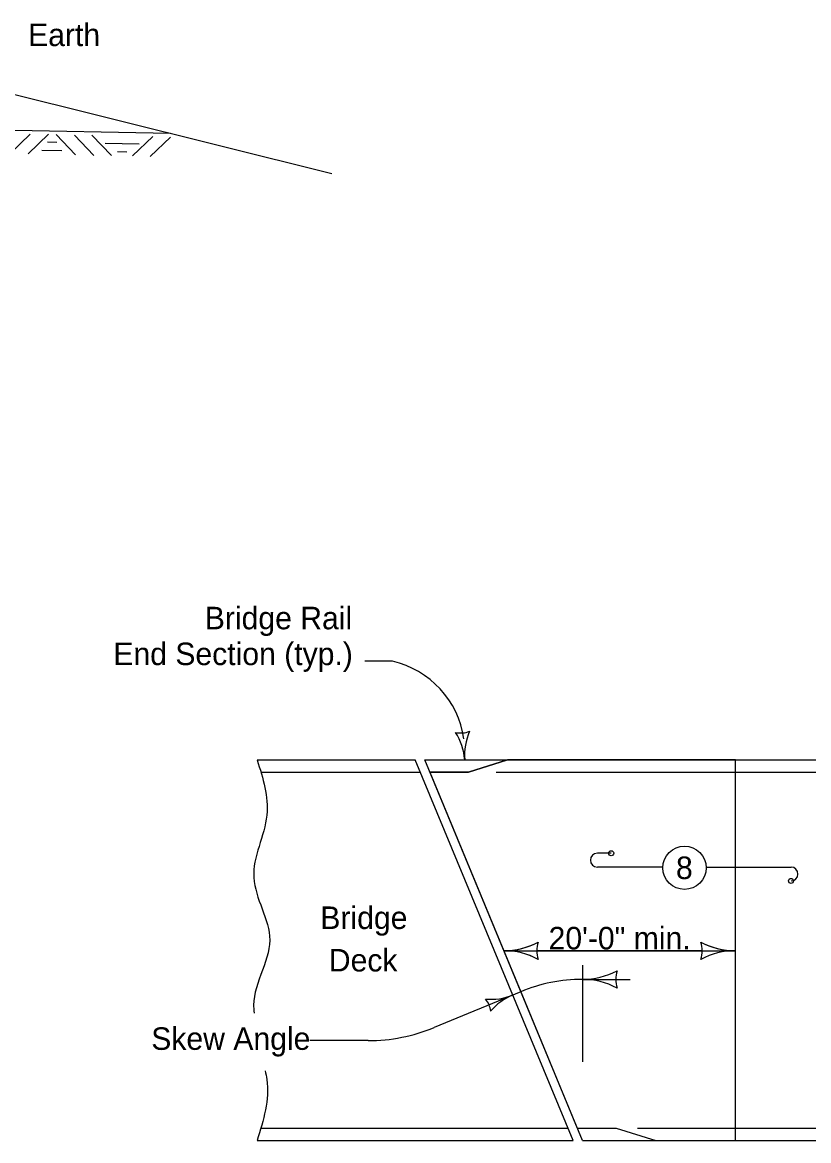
# Model space of a CAD drawing. Extents: x -2135039 to -2124495, y -2139046 to -2132546.
# Drawn here: x -2126600 to -2126042, y -2138086 to -2137292 of the extents above; entities that cross this region are included whole.
import ezdxf

# ---------------------------------------------------------------- set-up
doc = ezdxf.new("R2010")
doc.units = 0
for name, color, linetype in [('BridgeSuperStructureExisting', 7, 'Continuous'), ('dsnCellElements', 7, 'Continuous'), ('dsnStdLabel', 7, 'Continuous')]:
    doc.layers.add(name, color=color, linetype=linetype)

msp = doc.modelspace()

# ---------------------------------------------------------------- linework, layer by layer
at = {"layer": 'BridgeSuperStructureExisting'}
for p, q in [((-2126628.92, -2137337.22), (-2126380.66, -2137399.31)), ((-2126673.14, -2137367.07), (-2126495.29, -2137370.64)), ((-2126594.91, -2137371.29), (-2126609.33, -2137385.15)), ((-2126581.9, -2137371.33), (-2126596.32, -2137385.18)), ((-2126576.49, -2137371.44), (-2126562.63, -2137385.86)), ((-2126563.49, -2137371.92), (-2126549.63, -2137386.35)), ((-2126551.03, -2137371.95), (-2126537.18, -2137386.37)), ((-2126507.82, -2137372.81), (-2126522.24, -2137386.67)), ((-2126495.38, -2137373.29), (-2126509.8, -2137387.15)), ((-2126337.71, -2137745.6), (-2126357.21, -2137745.6)), ((-2126433.75, -2137815.7), (-2126321.65, -2137815.7)), ((-2126209.48, -2138086.06), (-2126321.47, -2137815.7)), ((-2126202.81, -2138086.06), (-2126314.79, -2137815.7)), ((-2126314.79, -2137815.7), (-2126094.13, -2137815.7)), ((-2126256.03, -2137815.7), (-2126283.71, -2137824.41)), ((-2126283.71, -2137824.41), (-2126256.03, -2137815.7)), ((-2126094.13, -2137815.7), (-2126256.03, -2137815.7)), ((-2126094.13, -2137877.15), (-2126094.13, -2137815.7)), ((-2126094.13, -2138077.2), (-2126094.13, -2137815.7)), ((-2126094.13, -2137815.7), (-2125731.85, -2137815.77)), ((-2126430.89, -2137824.41), (-2126317.95, -2137824.41)), ((-2126311.27, -2137824.41), (-2126283.71, -2137824.41)), ((-2126283.71, -2137824.41), (-2126311.19, -2137824.41)), ((-2126311.19, -2137824.41), (-2126258.65, -2137951.23)), ((-2126264.16, -2137824.41), (-2125636.52, -2137824.42)), ((-2126182.39, -2137882.02), (-2126192.22, -2137882.02)), ((-2126145.73, -2137891.86), (-2126192.21, -2137891.86)), ((-2126115.01, -2137891.86), (-2126054.71, -2137891.86)), ((-2126258.8, -2137951.23), (-2126094.13, -2137951.23)), ((-2126258.65, -2137951.23), (-2126258.03, -2137951.23)), ((-2126235.18, -2137951.23), (-2126117.75, -2137951.23)), ((-2126117.75, -2137951.23), (-2126235.18, -2137951.23)), ((-2126094.89, -2137951.23), (-2126094.13, -2137951.23)), ((-2126202.81, -2137961.59), (-2126202.81, -2138030.26)), ((-2126202.81, -2137971.6), (-2126168.84, -2137971.6)), ((-2126246.61, -2137980.32), (-2126308, -2138005.75)), ((-2126355.03, -2138015.11), (-2126396.45, -2138015.11)), ((-2126094.13, -2138086.06), (-2126094.13, -2138019.17)), ((-2126431.02, -2138077.2), (-2126213.15, -2138077.2)), ((-2126206.47, -2138077.2), (-2126178.91, -2138077.2)), ((-2126206.47, -2138077.2), (-2126178.91, -2138077.2)), ((-2126178.91, -2138077.2), (-2126150.78, -2138086.06)), ((-2126178.91, -2138077.2), (-2126150.78, -2138086.06)), ((-2126163.79, -2138077.2), (-2125632.85, -2138077.22)), ((-2126433.75, -2138086.06), (-2126209.48, -2138086.06)), ((-2126202.81, -2138086.06), (-2126094.13, -2138086.06)), ((-2126150.78, -2138086.06), (-2126094.13, -2138086.06)), ((-2126094.13, -2138086.06), (-2125731.85, -2138086.13))]:
    msp.add_line(p, q, dxfattribs=at)
for points in [[(-2126582.57, -2137376.81), (-2126576.04, -2137376.94)], [(-2126541.56, -2137377.61), (-2126517.51, -2137378.1)], [(-2126586.51, -2137382.59), (-2126572.33, -2137382.88)], [(-2126532.92, -2137383.59), (-2126526.39, -2137383.72)], [(-2126094.13, -2137951.23), (-2126094.13, -2137891.86), (-2126094.13, -2137877.15), (-2126094.13, -2137824.41), (-2126094.13, -2137815.7)], [(-2126258.65, -2137951.24), (-2126246.6, -2137980.32), (-2126206.47, -2138077.2)], [(-2126094.13, -2138086.06), (-2126094.13, -2138077.2), (-2126094.13, -2138024.62), (-2126094.13, -2137951.24)], [(-2126094.13, -2137951.24), (-2126094.13, -2137951.24)]]:
    msp.add_lwpolyline(points, dxfattribs=at)
msp.add_circle((-2126130.34, -2137892.33), 15.36, dxfattribs=at)
msp.add_circle((-2126130.34, -2137892.33), 15.36, dxfattribs=at)
for centre, radius, start, end in [((-2126352.83, -2137810.52), 66.66, 8.48278, 76.88228), ((-2126192.22, -2137886.94), 4.92, 90, 270), ((-2126054.71, -2137896.77), 4.92, 270, 90), ((-2126258.8, -2137899.01), 52.23, 270, 298.07249), ((-2126258.8, -2137899.01), 52.23, 270.84325, 298.07249), ((-2126215.01, -2137951.24), 20.17, 162.26665, 179.98394), ((-2126215.01, -2137951.24), 20.17, 162.26665, 197.73335), ((-2126137.92, -2137951.24), 20.17, 0.01606, 17.73335), ((-2126094.13, -2137899.01), 52.23, 241.92751, 269.15673), ((-2126137.92, -2137951.24), 20.17, 342.26665, 17.73335), ((-2126094.13, -2137899.01), 52.23, 241.92751, 270), ((-2126258.8, -2138003.46), 52.23, 61.92751, 90), ((-2126258.8, -2138003.46), 52.23, 61.92751, 89.8364), ((-2126215.01, -2137951.24), 20.17, 179.98394, 197.73335), ((-2126137.92, -2137951.24), 20.17, 342.26665, 0.01606), ((-2126094.13, -2138003.46), 52.23, 90.0176, 118.07249), ((-2126094.13, -2138003.46), 52.23, 90, 118.07249), ((-2126094.13, -2137899.01), 52.23, 269.9824, 270), ((-2126202.81, -2137919.38), 52.23, 270, 298.07249), ((-2126202.81, -2137919.38), 52.23, 270, 298.07249), ((-2126159.02, -2137971.61), 20.17, 162.26665, 197.73335), ((-2126159.02, -2137971.61), 20.17, 162.26665, 197.73335), ((-2126202.81, -2138086.06), 114.45, 90, 112.5), ((-2126202.81, -2138023.84), 52.23, 61.92751, 90), ((-2126202.81, -2138023.84), 52.23, 61.92751, 90), ((-2126267.67, -2137945.56), 40.18, 264.4275, 292.49999), ((-2126236.93, -2138019.8), 40.18, 112.49999, 140.57248), ((-2126283.42, -2137995.57), 15.52, 4.76664, 40.23334), ((-2126355.03, -2137892.22), 122.89, 270, 292.49999)]:
    msp.add_arc(centre, radius, start, end, dxfattribs=at)
for points in [[(-2126433.74, -2137815.71), (-2126426.89, -2137854.91), (-2126436.17, -2137899.28), (-2126424.83, -2137943.64), (-2126436.17, -2137993.16), (-2126435.88, -2137995.55)], [(-2126428.05, -2138036.47), (-2126426.89, -2138042.68), (-2126433.75, -2138086.06)]]:
    msp.add_spline(points, degree=3, dxfattribs=at)
at = {"layer": 'dsnCellElements'}
for centre in [(-2126182.39, -2137882.02), (-2126054.71, -2137901.69)]:
    msp.add_circle(centre, 1.78, dxfattribs=at)
for centre, radius, start, end in [((-2126289.09, -2137780.17), 16.42, 256.63311, 292.09982), ((-2126328.75, -2137818.93), 42.5, 4.36647, 32.43895), ((-2126244, -2137812.46), 42.5, 156.29398, 184.36647)]:
    msp.add_arc(centre, radius, start, end, dxfattribs=at)

# ---------------------------------------------------------------- texts
at = {"layer": 'BridgeSuperStructureExisting'}
for s, p in [('Bridge Rail', (-2126470.93, -2137722.93)), ('End Section (typ.)', (-2126535.86, -2137748.38))]:
    msp.add_text(s, height=16, dxfattribs=at).set_placement(p)
at = {"layer": 'dsnStdLabel'}
for s, p in [('Earth', (-2126596.38, -2137308.7)), ('8', (-2126136.38, -2137900.33)), ('Bridge', (-2126388.89, -2137935.81)), ('20\'-0" min.', (-2126226.83, -2137950.31)), ('Deck', (-2126382.85, -2137965.99)), ('Skew Angle', (-2126508.94, -2138021.65))]:
    msp.add_text(s, height=16, dxfattribs=at).set_placement(p)

doc.saveas('drawing.dxf')
